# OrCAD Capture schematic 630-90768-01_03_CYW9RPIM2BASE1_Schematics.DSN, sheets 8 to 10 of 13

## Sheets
8 05. CM4 HDMI & Fan Control: size B
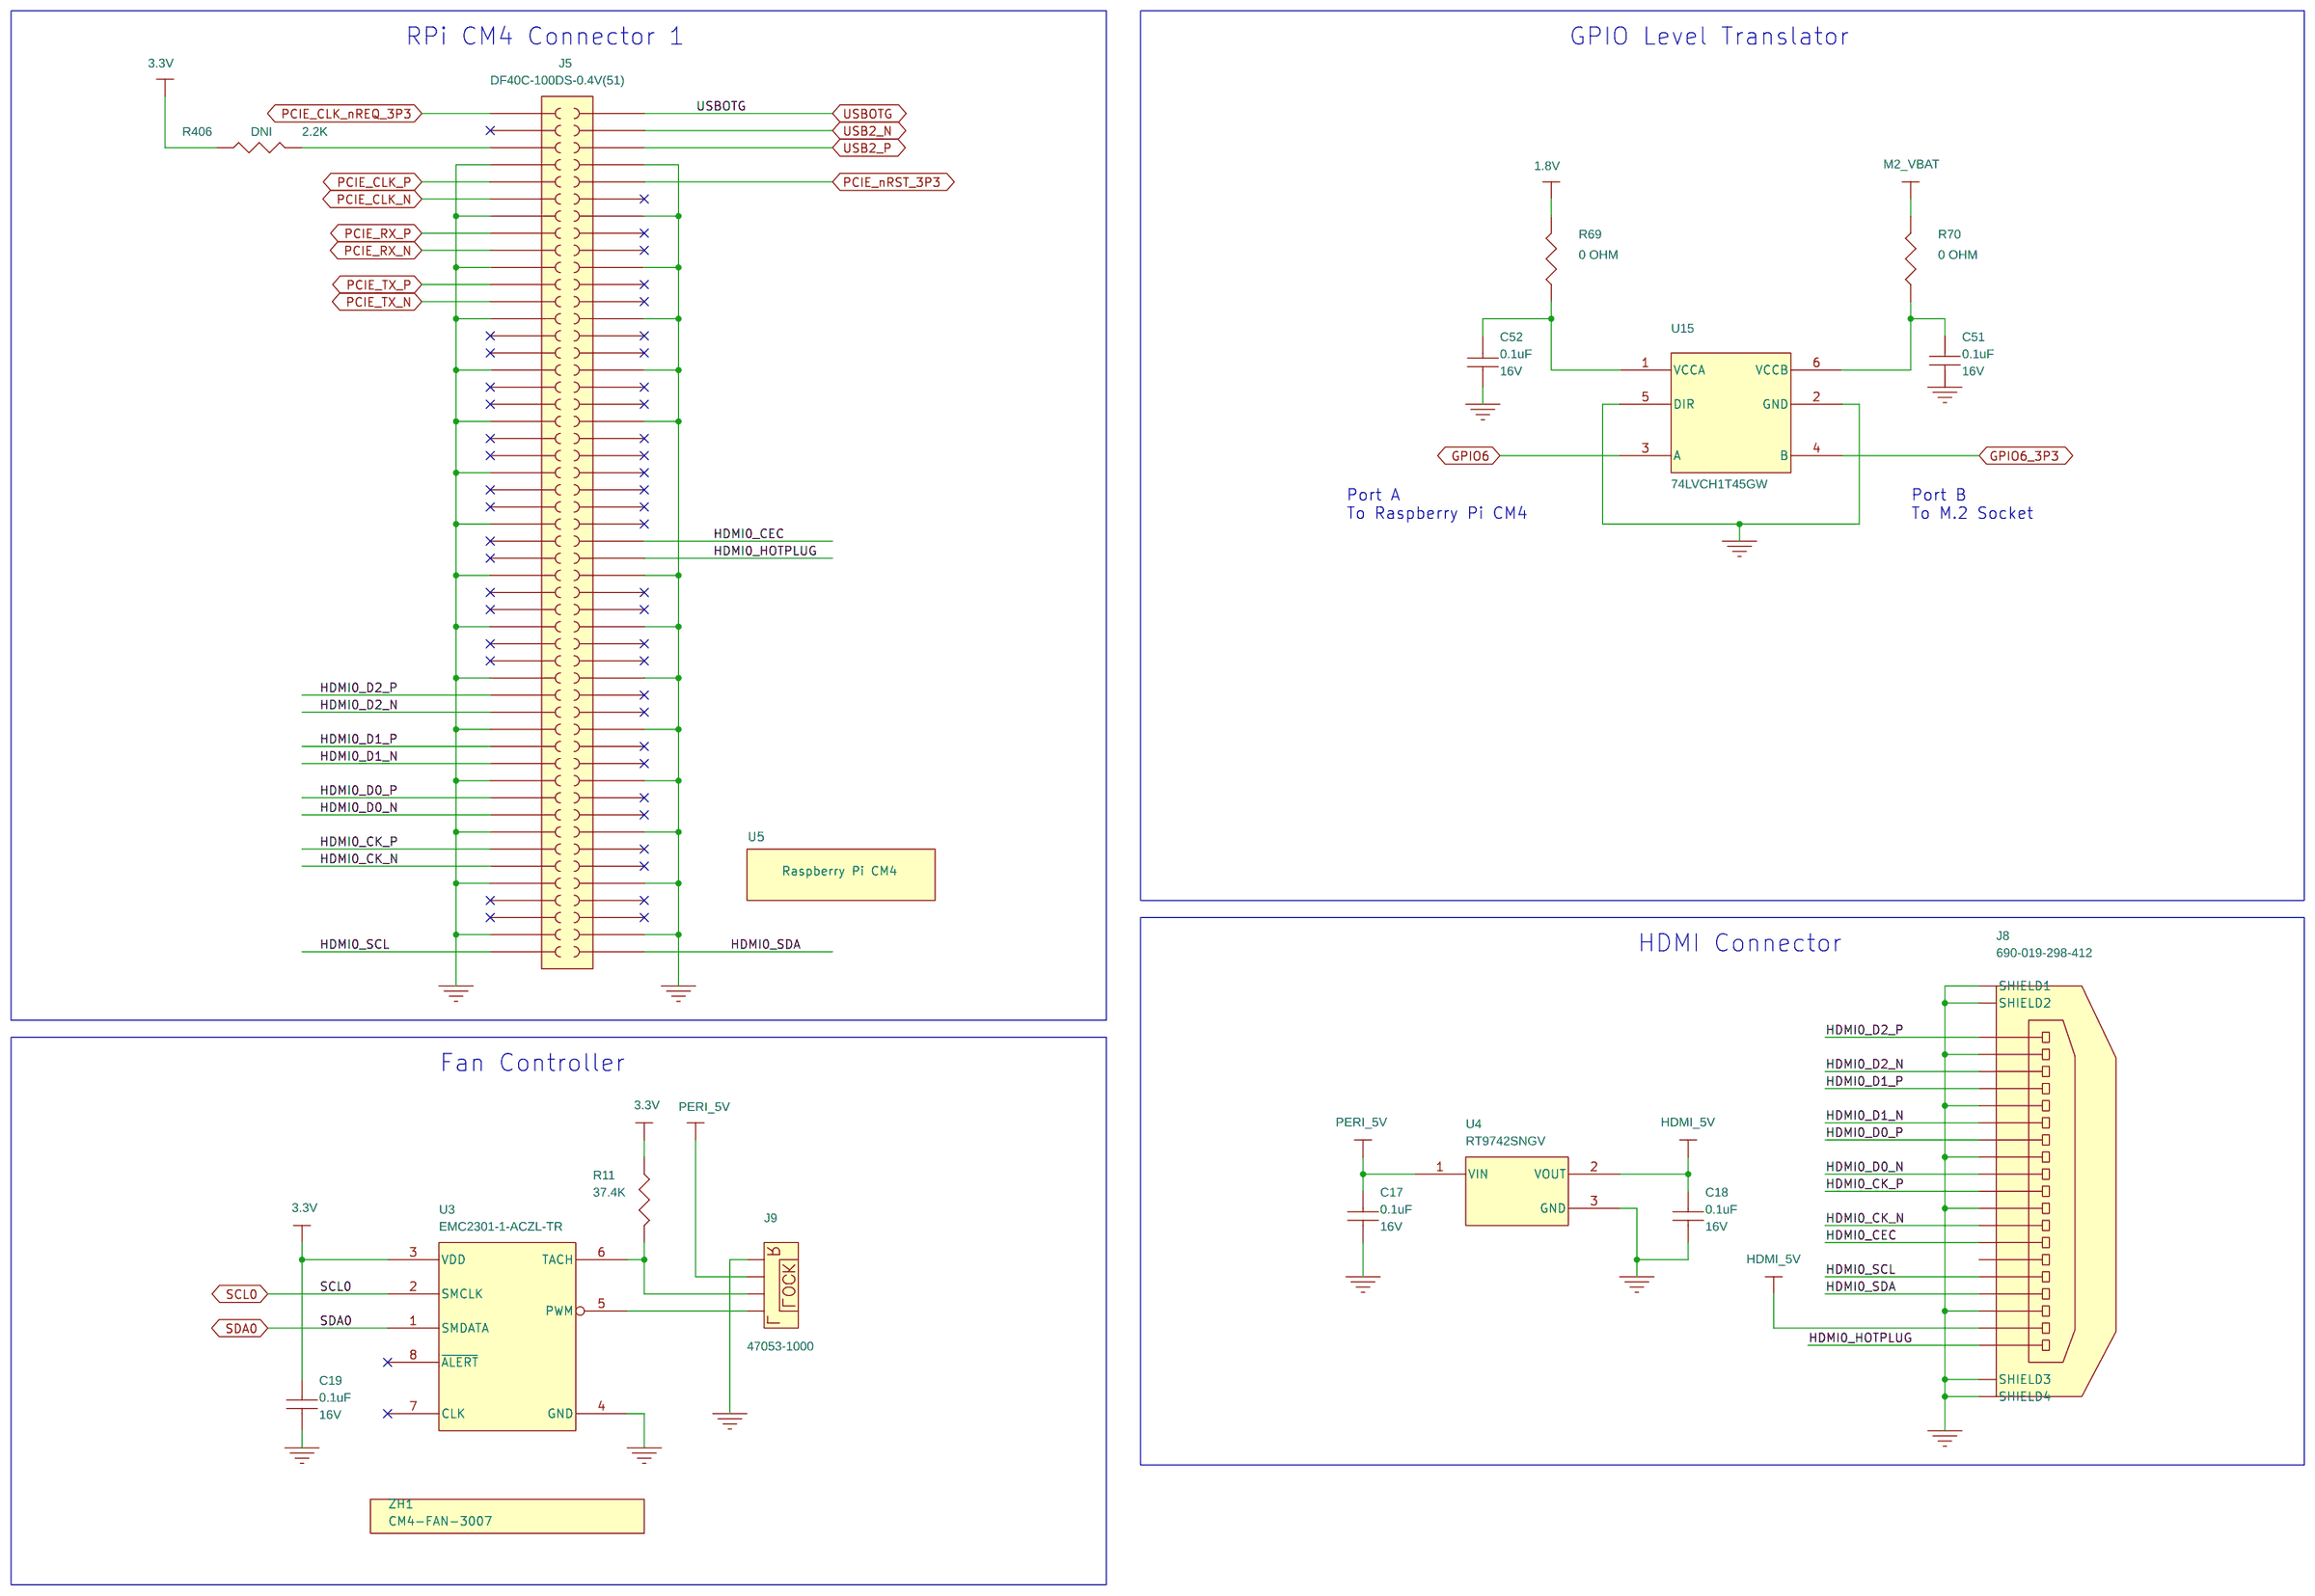
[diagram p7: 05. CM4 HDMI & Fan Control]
9 06. CM4 GPIO & Ethernet: size B
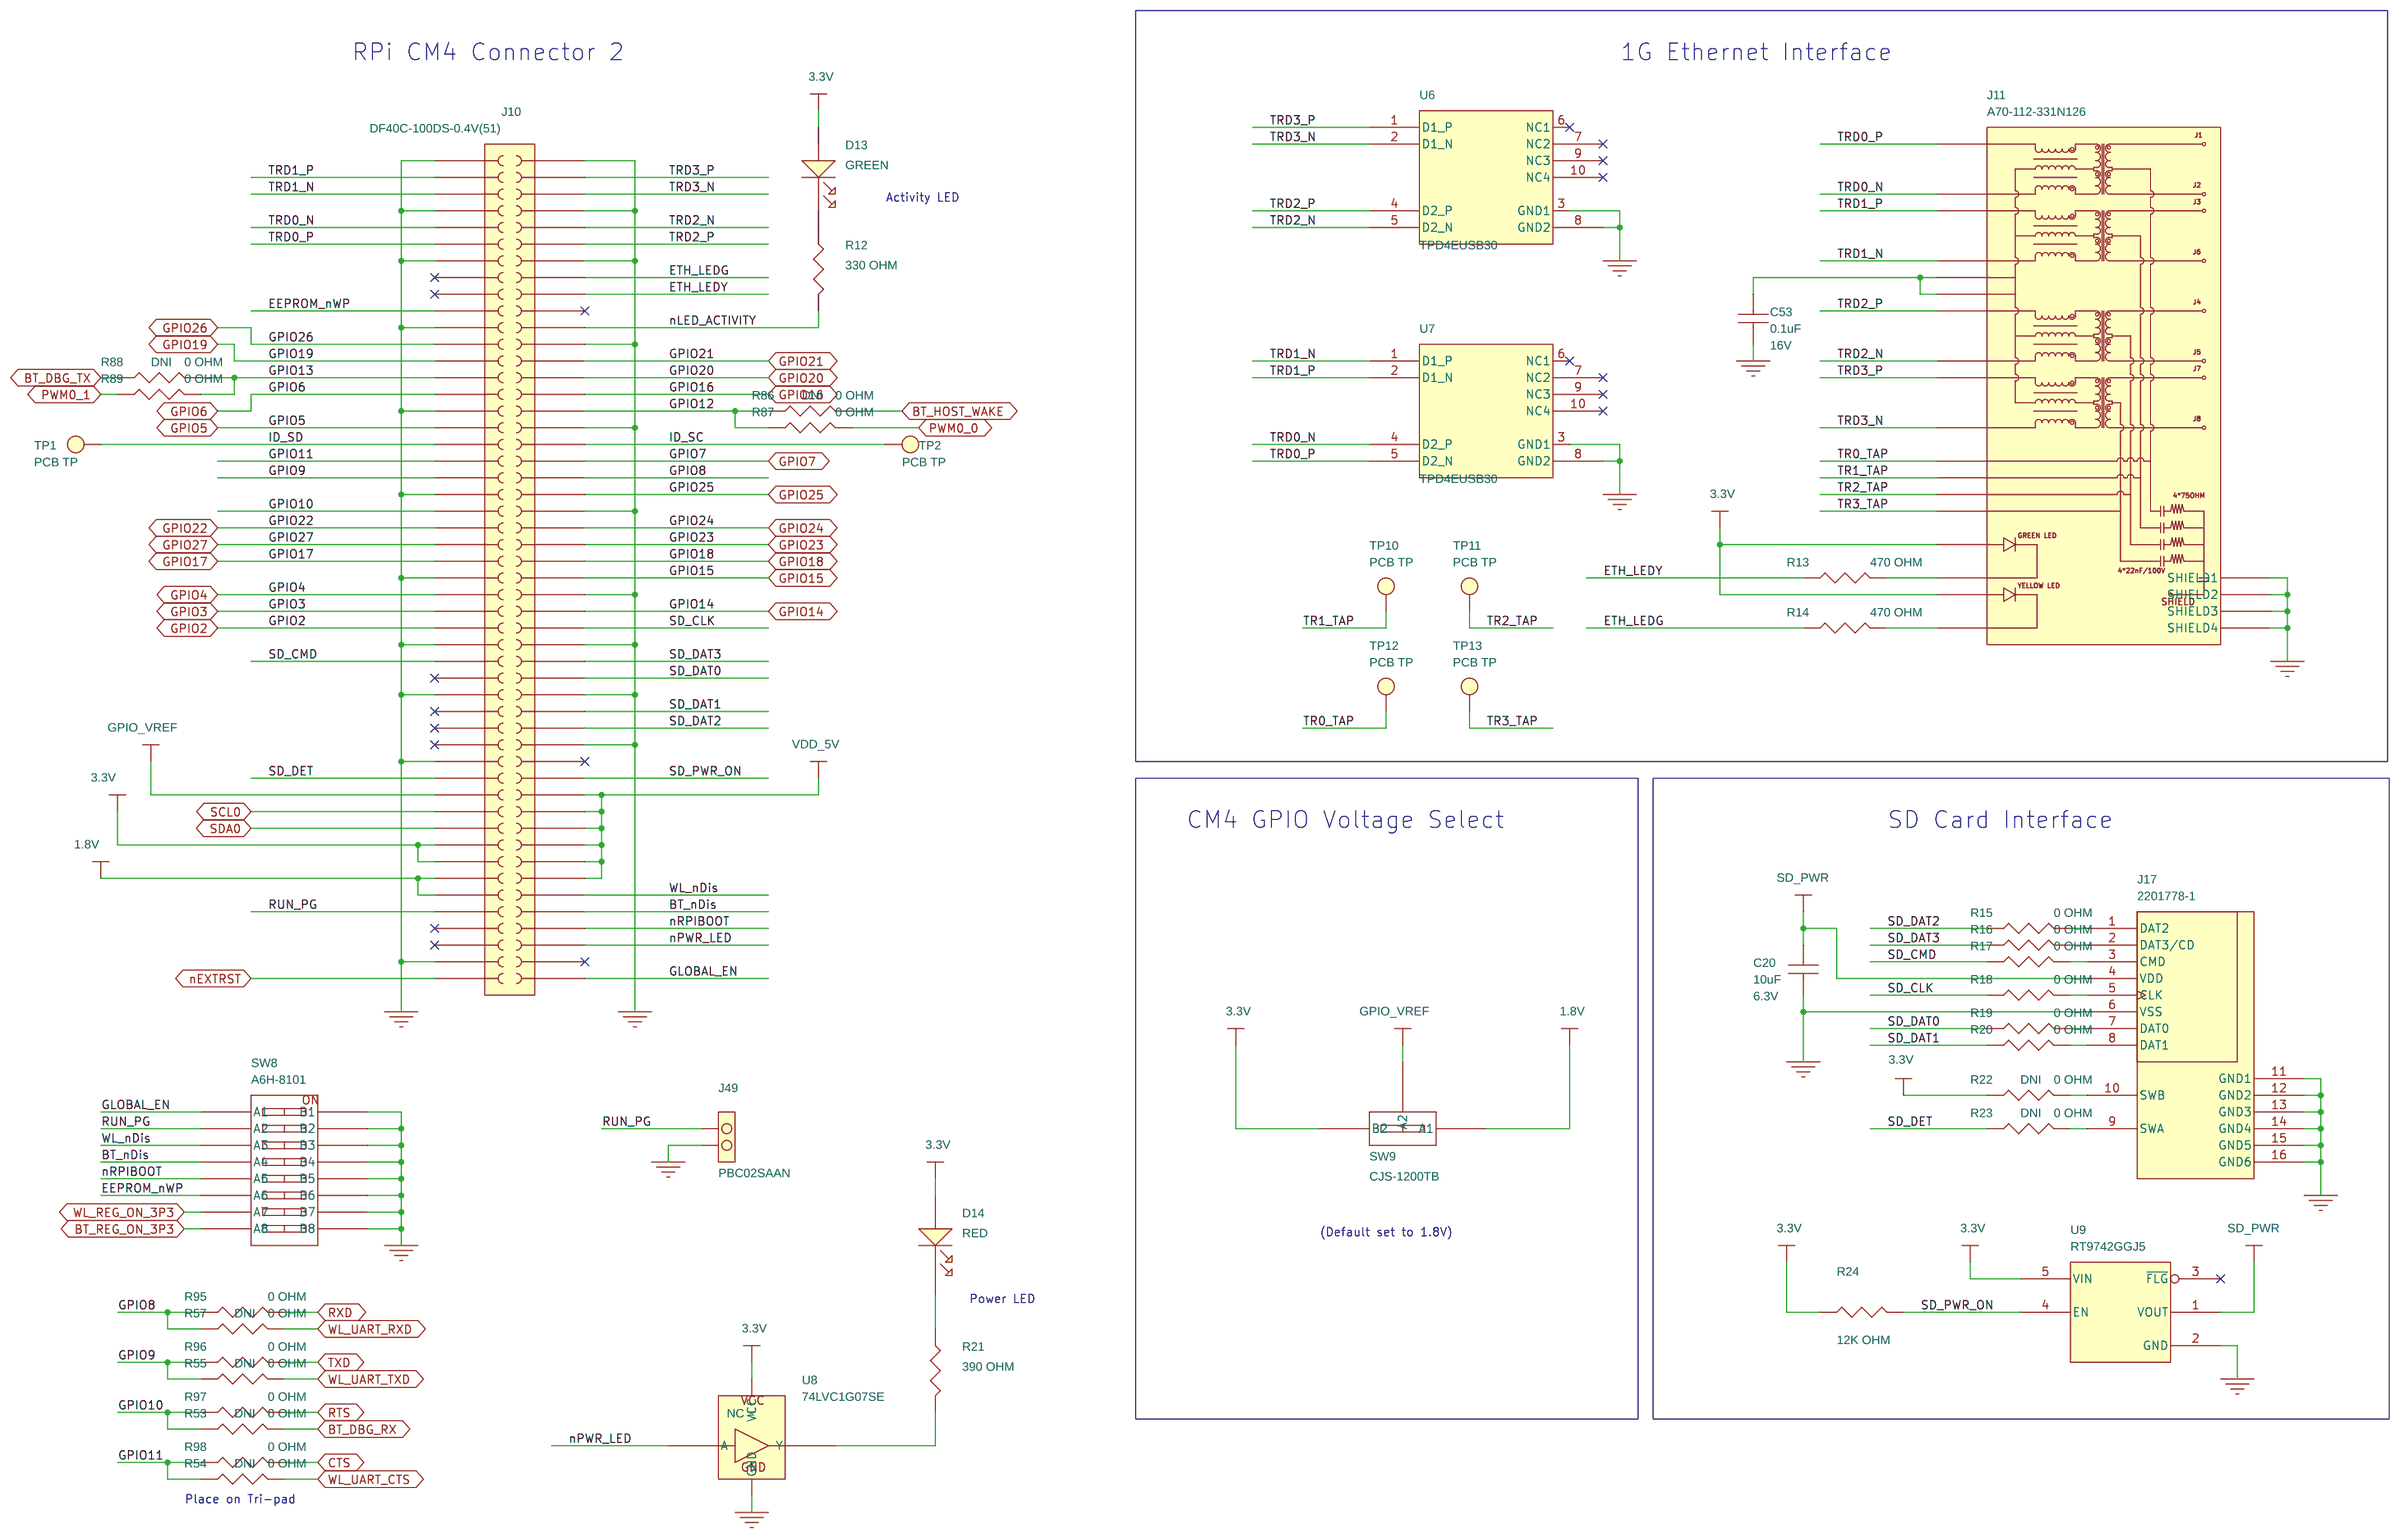
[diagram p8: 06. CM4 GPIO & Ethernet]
10 07. M.2 Interface: size B
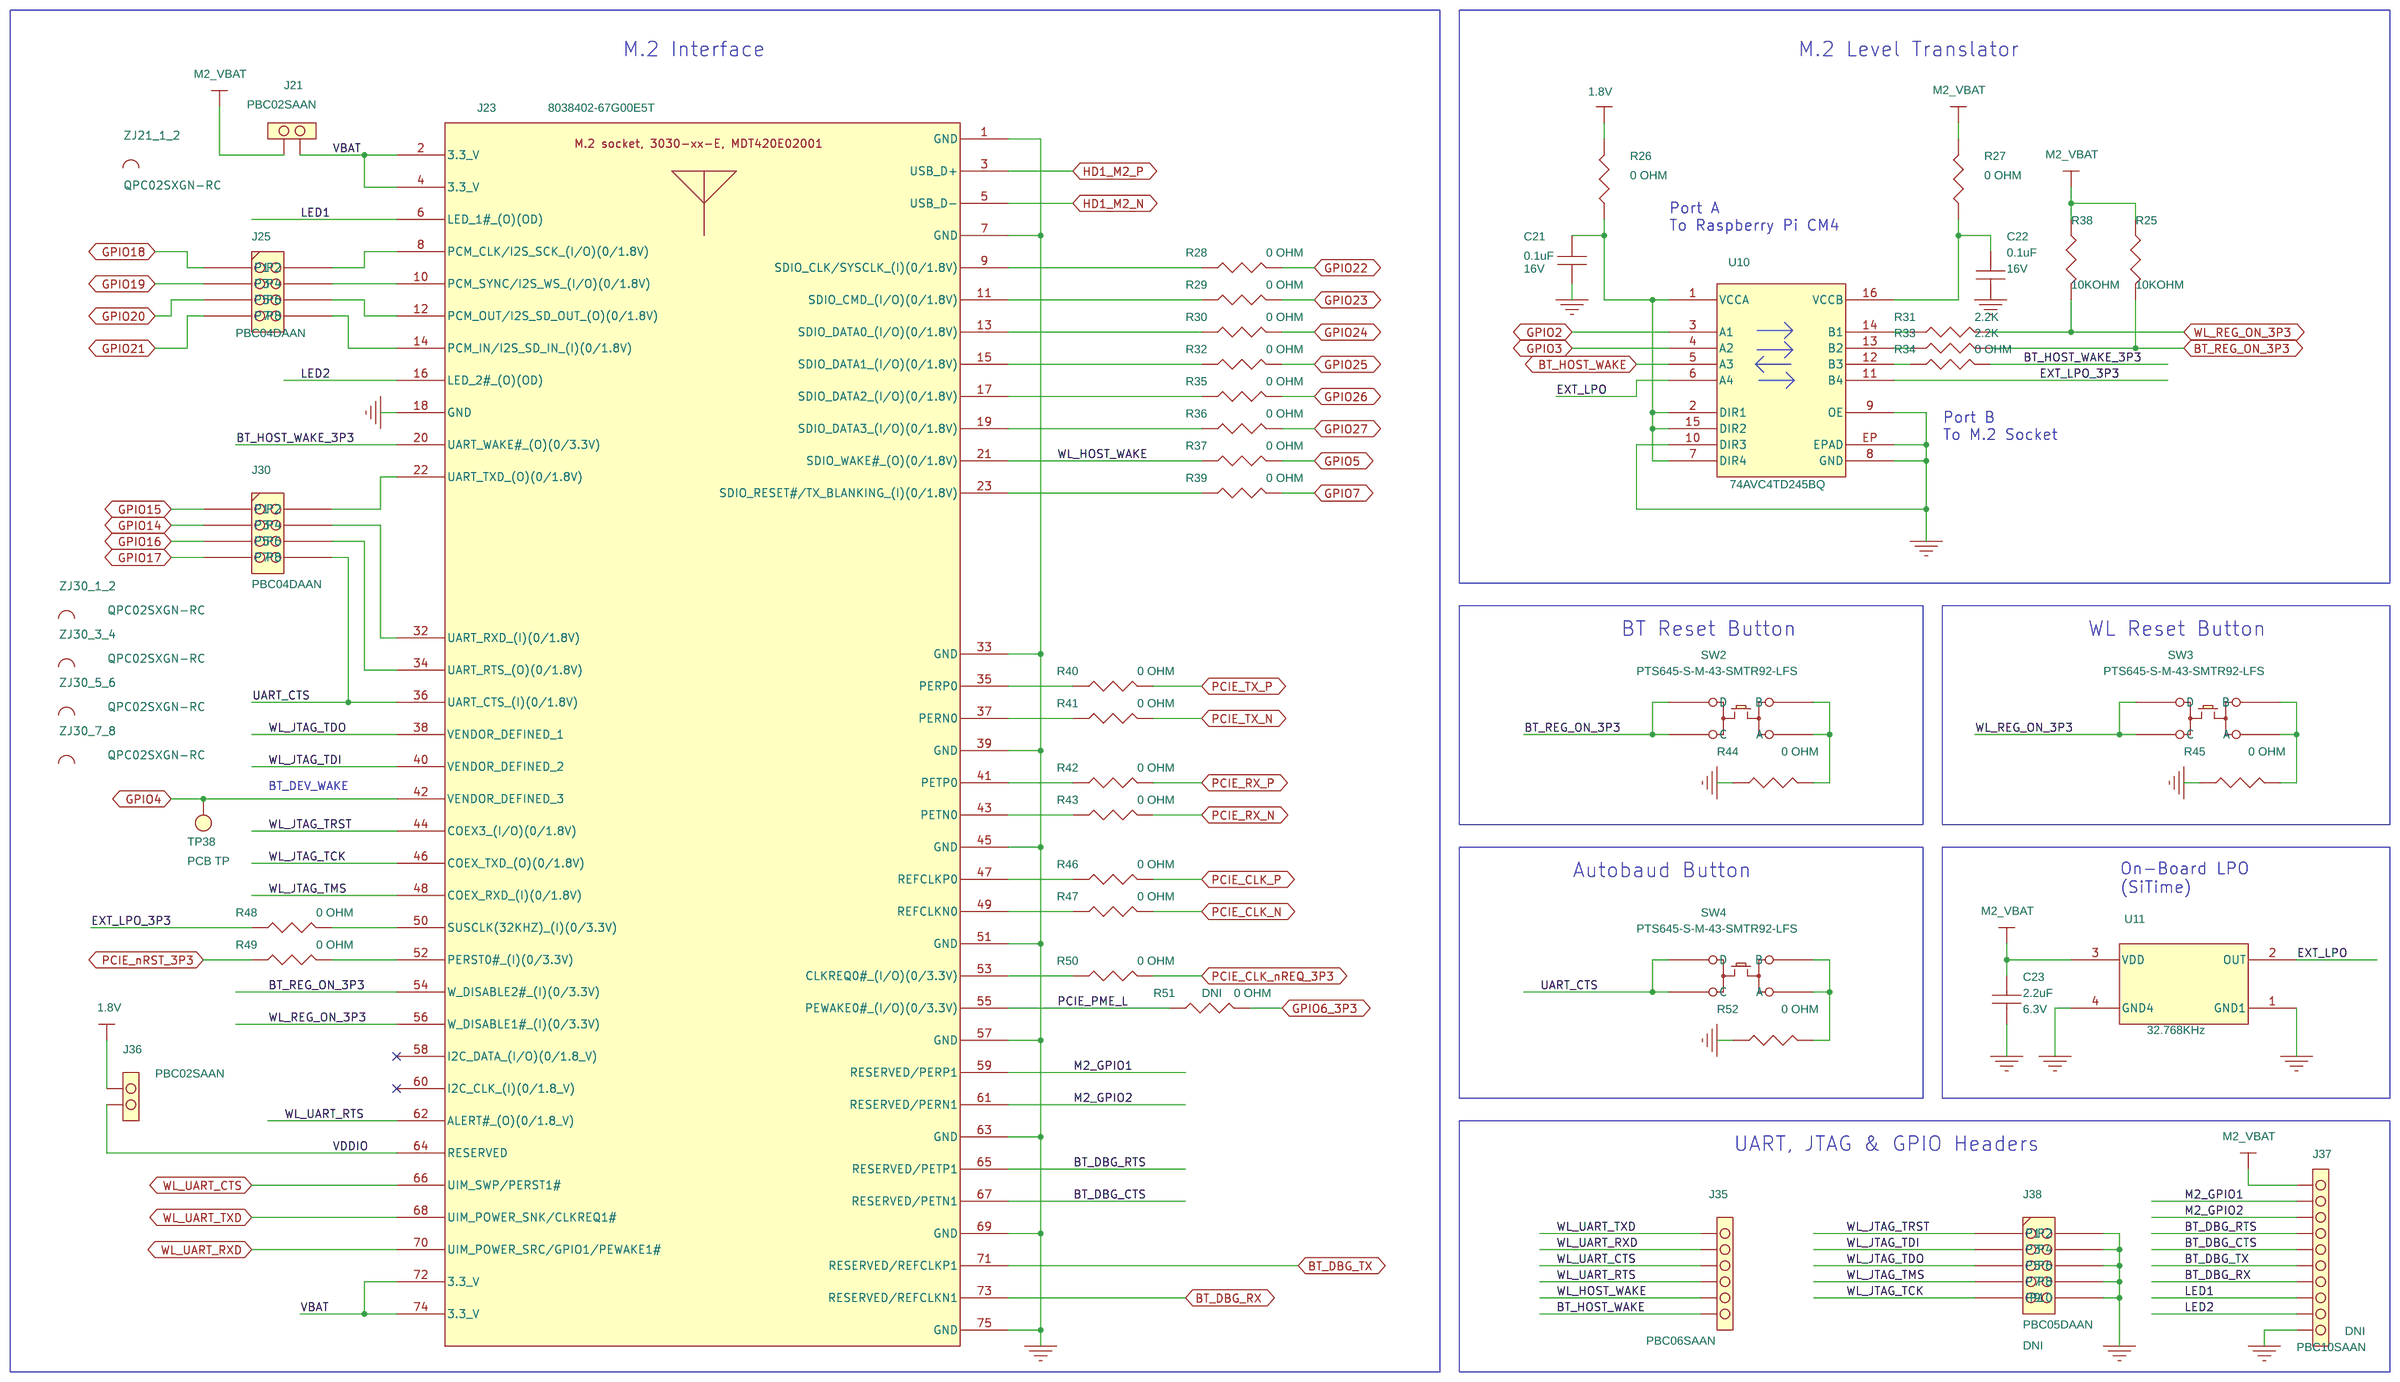
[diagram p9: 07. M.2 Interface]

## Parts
sheet 05. CM4 HDMI & Fan Control
C17  0.1uF  [CAPC1005_IS0402Q]
C18  0.1uF  [CAPC1005_IS0402Q]
C19  0.1uF  [CAPC1005_IS0402Q]
C51  0.1uF  [CAPC1005_IS0402Q]
C52  0.1uF  [CAPC1005_IS0402Q]
J5  DF40C-100DS-0.4V(51)  [con2x50_0p4_DF40C-100DS]
J8  690-019-298-412  [CON1X19_0P5_690-019-298-412]
J9  47053-1000  [molex_47053-1000]
R11  37.4K  [RESC1005_IS0402Q]
R69  0 OHM  [RESC1005_IS0402Q]
R70  0 OHM  [RESC1005_IS0402Q]
R406  2.2K  [RESC1005_IS0402Q]
U3  EMC2301-1-ACZL-TR  [msop65p490x110-8m]
U4  RT9742SNGV  [SOT23_1_2_3]
U5  Raspberry Pi CM4  [MOD-raspberry_PI_CM4]
U15  74LVCH1T45GW  [SC70-6_SC88-6_1_2_3_4_5_6]
ZH1  CM4-FAN-3007  [NA]
sheet 06. CM4 GPIO & Ethernet
C20  10uF  [CAPC1005_IS0402Q]
C53  0.1uF  [CAPC1005_IS0402Q]
D13  GREEN  [LEDC1608Q]
D14  RED  [LEDC1608Q]
J10  DF40C-100DS-0.4V(51)  [con2x50_0p4_DF40C-100DS]
J11  A70-112-331N126  [RJ45-A70-112-331N126]
J17  2201778-1  [CONmSD_2201778-1]
J49  PBC02SAAN  [CTST254PSS2]
R12  330 OHM  [RESC1005_IS0402Q]
R13  470 OHM  [RESC1005_IS0402Q]
R14  470 OHM  [RESC1005_IS0402Q]
R15  0 OHM  [RESC1005_IS0402Q]
R16  0 OHM  [RESC1005_IS0402Q]
R17  0 OHM  [RESC1005_IS0402Q]
R18  0 OHM  [RESC1005_IS0402Q]
R19  0 OHM  [RESC1005_IS0402Q]
R20  0 OHM  [RESC1005_IS0402Q]
R21  390 OHM  [RESC1005_IS0402Q]
R22  0 OHM  [RESC1005_IS0402Q]
R23  0 OHM  [RESC1005_IS0402Q]
R24  12K OHM  [RESC1005_IS0402Q]
R53  0 OHM  [RESC1005_IS0402Q]
R54  0 OHM  [RESC1005_IS0402Q]
R55  0 OHM  [RESC1005_IS0402Q]
R57  0 OHM  [RESC1005_IS0402Q]
R86  0 OHM  [RESC1005_IS0402Q]
R87  0 OHM  [RESC1005_IS0402Q]
R88  0 OHM  [RESC1005_IS0402Q]
R89  0 OHM  [RESC1005_IS0402Q]
R95  0 OHM  [RESC1005_IS0402Q]
R96  0 OHM  [RESC1005_IS0402Q]
R97  0 OHM  [RESC1005_IS0402Q]
R98  0 OHM  [RESC1005_IS0402Q]
SW8  A6H-8101  [SWDPS16_OMRON_A6H-8101]
SW9  CJS-1200TB  [SWDPS2_CJS]
TP1  PCB TP  [tp102c]
TP2  PCB TP  [tp102c]
TP10  PCB TP  [tp102c]
TP11  PCB TP  [tp102c]
TP12  PCB TP  [tp102c]
TP13  PCB TP  [tp102c]
U6  TPD4EUSB30  [uson10_p100x250_050mm]
U7  TPD4EUSB30  [uson10_p100x250_050mm]
U8  74LVC1G07SE  [sot65p210x215-6m]
U9  RT9742GGJ5  [tsot23-5_1_2_3_4_5]
sheet 07. M.2 Interface
C21  0.1uF  [CAPC1005_IS0402Q]
C22  0.1uF  [CAPC1005_IS0402Q]
C23  2.2uF  [CAPC1005_IS0402Q]
J21  PBC02SAAN  [CTST254PSS2]
J23  8038402-67G00E5T  [M_2_2230-XX-E_MDT420E02001]
J25  PBC04DAAN  [CTST254PDS8]
J30  PBC04DAAN  [CTST254PDS8]
J35  PBC06SAAN  [CTST254PSS6]
J36  PBC02SAAN  [CTST254PSS2]
J37  PBC10SAAN  [CTST254PSS10]
J38  PBC05DAAN  [CTST254PDS10]
R25  10KOHM  [RESC1005_IS0402Q]
R26  0 OHM  [RESC1005_IS0402Q]
R27  0 OHM  [RESC1005_IS0402Q]
R28  0 OHM  [RESC1005_IS0402Q]
R29  0 OHM  [RESC1005_IS0402Q]
R30  0 OHM  [RESC1005_IS0402Q]
R31  2.2K  [RESC1005_IS0402Q]
R32  0 OHM  [RESC1005_IS0402Q]
R33  2.2K  [RESC1005_IS0402Q]
R34  0 OHM  [RESC1005_IS0402Q]
R35  0 OHM  [RESC1005_IS0402Q]
R36  0 OHM  [RESC1005_IS0402Q]
R37  0 OHM  [RESC1005_IS0402Q]
R38  10KOHM  [RESC1005_IS0402Q]
R39  0 OHM  [RESC1005_IS0402Q]
R40  0 OHM  [RESC1005_IS0402Q]
R41  0 OHM  [RESC1005_IS0402Q]
R42  0 OHM  [RESC1005_IS0402Q]
R43  0 OHM  [RESC1005_IS0402Q]
R44  0 OHM  [RESC1005_IS0402Q]
R45  0 OHM  [RESC1005_IS0402Q]
R46  0 OHM  [RESC1005_IS0402Q]
R47  0 OHM  [RESC1005_IS0402Q]
R48  0 OHM  [RESC1005_IS0402Q]
R49  0 OHM  [RESC1005_IS0402Q]
R50  0 OHM  [RESC1005_IS0402Q]
R51  0 OHM  [RESC1005_IS0402Q]
R52  0 OHM  [RESC1005_IS0402Q]
SW2  PTS645-S-M-43-SMTR92-LFS  [swpbs4_pts645_smt]
SW3  PTS645-S-M-43-SMTR92-LFS  [swpbs4_pts645_smt]
SW4  PTS645-S-M-43-SMTR92-LFS  [swpbs4_pts645_smt]
TP38  PCB TP  [tp102c]
U10  74AVC4TD245BQ  [qfn50p350x250_16_hs200x100]
U11  32.768KHz  [xtals4_1p0x0p41_1m55x0m85]
ZJ21_1_2  QPC02SXGN-RC  [NA]
ZJ30_1_2  QPC02SXGN-RC  [NA]
ZJ30_3_4  QPC02SXGN-RC  [NA]
ZJ30_5_6  QPC02SXGN-RC  [NA]
ZJ30_7_8  QPC02SXGN-RC  [NA]

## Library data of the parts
C17-C19 C21 C22 C51-C53 = CAP: CAP, CER, 0402, 0.1uF, 10%, 16V, X7R; Assembly Instructions: <Assembly Instructions>; BRCM PN: 520157-00; CYPN: 510-90749-01; Enviromental: RoHS; FPLIST: CAPC1005_IS0402Q,CAPC1005_IS0402N,capc1005_is0402q_HP; PART TYPE: Ceramic Capacitor; Size: 0402; Status: APPROVED; TC: X7R; Tolerance: 10%; VOLTAGE: 16V; vendor_1: DARFON; vendor_2: DARFON; vendor_3: Walsin; vendor_4: Samsung; vendor_5: Murata Electronics North America; vendor_part_number_1: C1005X7R104KETS; vendor_part_number_2: C1005X7R104KETA; vendor_part_number_3: 0402B104K160CT; vendor_part_number_4: CL05B104KO5NNNC; vendor_part_number_5: GRM155R71C104KA88D -NRND-; Datasheet: \\shasdv005.infineon.com\CMU\CMU_ORCAD_CIS_LIB\CYPRESS_CIS_DATABASE\datasheet\Murata_GRM155R71C104KA88D.pdf
J5 J10 = SKT_100_ODD_EVEN_J: CONN, BOARD TO BOARD/BOARD TO FPC, RECEPTACLE, 2X50, 0.4MM PITCH, 1.5MM STACKING HEIGHT, V/T, SMT; Assembly Instructions: <Assembly Instructions>; CYPN: 720-90645-01; Enviromental: RoHS; PART TYPE: HEADER_FEMALE; Status: APPROVED; vendor_1: HIROSE; Datasheet: \\shasdv005.infineon.com\CMU\CMU_ORCAD_CIS_LIB\CYPRESS_CIS_DATABASE\datasheet\DF40C-100DS-0.4V(51).pdf
J8 = CONN_HDMI_TYPE-A_19P: CON, HDMI, TYPE A, F, R/A, 19 POS, 0.5mm PITCH, 15.0x12.14x6.08mm, SMT; Assembly Instructions: <Assembly Instructions>; CYPN: 720-90650-01; Enviromental: RoHS; PART TYPE: HDMI; Status: APPROVED; vendor_1: EDAC; Datasheet: \\shasdv005.infineon.com\CMU\CMU_ORCAD_CIS_LIB\CYPRESS_CIS_DATABASE\datasheet\690-019-298-412.pdf
J9 = HDR1X4-LOCK-1R-J: CON, HDR, T/H, M, STR, 1x4P, 2.54mm PITCH, 3.5mmTL, 7.5mmPH, W/FRICTION; Assembly Instructions: <Assembly Instructions>; CYPN: 710-90172-01; Enviromental: RoHS; PART TYPE: HEADER_MALE; Status: APPROVED; vendor_1: Molex; Datasheet: \\shasdv005.infineon.com\CMU\CMU_ORCAD_CIS_LIB\CYPRESS_CIS_DATABASE\datasheet\470531000_sd.pdf
R11 = RES: RES, THK, 0402, 37.4K, 1%, 63mW, 50V; Assembly Instructions: <Assembly Instructions>; BRCM PN: 551066-00; CYPN: 500-91030-01; Enviromental: RoHS; FPLIST: RESC1005_IS0402Q,RESC1005_IS0402N; PART TYPE: THICK FILM; Size: 0402; Status: APPROVED; Tolerance: 1%; vendor_1: CYNTEC; vendor_2: VIKING TECH; vendor_3: Walsin; vendor_4: Yageo America; vendor_part_number_1: PFR05S-3742-FNH; vendor_part_number_2: CR-02FL6--37K4AC; vendor_part_number_3: WR04X3742FTL; vendor_part_number_4: RC0402FR-0737K4L; Datasheet: \\shasdv005.infineon.com\CMU\CMU_ORCAD_CIS_LIB\CYPRESS_CIS_DATABASE\datasheet\RC0402FR-0737K4L.pdf
R26 R27 R69 R70 = RES: RES, THK, 0402, 0, 1%, HI POWER, 125mW; BRCM PN: 553942-00; CYPN: 500-90992-01; Enviromental: RoHS; FPLIST: RESC1005_IS0402Q,RESC1005_IS0402N; PART TYPE: THICK FILM; Size: 0402; Status: APPROVED; Tolerance: 1%; vendor_1: VISHAY; vendor_2: Walsin; vendor_part_number_1: CRCW04020000Z0EDHP; vendor_part_number_2: WF04P000PTL; Datasheet: \\shasdv005.infineon.com\CMU\CMU_ORCAD_CIS_LIB\CYPRESS_CIS_DATABASE\datasheet\CRCW04020000Z0EDHP.pdf
R406 = RES: RES, THK, 0402, 2.2K OHM, 5%, 63mW; Assembly Instructions: <Assembly Instructions>; BRCM PN: 559975-00; CYPN: 500-90839-01; DNI: DNI; Enviromental: RoHS; FPLIST: RESC1005_IS0402Q,RESC1005_IS0402N; PART TYPE: THICK FILM; Size: 0402; Status: APPROVED; Tolerance: 5%; vendor_1: CYNTEC; vendor_2: KOA Speer Electronics; vendor_3: Panasonic-ECG; vendor_4: RALEC; vendor_5: VIKING TECH; vendor_6: Walsin; vendor_part_number_1: PFR05S-222-JNH; vendor_part_number_2: RK73B1ETTP222J; vendor_part_number_3: ERJ-2GEJ222X; vendor_part_number_4: RTT02222JTH; vendor_part_number_5: CR-02JL6---2K2AC; vendor_part_number_6: WR04X222 JTL
U3 = EMC2301_MSOP8: IC, Single RPM-Based PWM Fan Controller, MSOP-8P; Assembly Instructions: <Assembly Instructions>; CYPN: 450-90680-01; Enviromental: RoHS; PART TYPE: CONTROLLER; Status: APPROVED; vendor_1: Microchip Technology; Datasheet: \\shasdv005.infineon.com\CMU\CMU_ORCAD_CIS_LIB\CYPRESS_CIS_DATABASE\datasheet\EMC2301-1-ACZL-TR.pdf
U4 = RT9742SNGV_SOT23_3: IC, POWER SWH, HIGH-SIDE, W/FLAG, 2.7V/6V, 0.5A, SOT23-3; Assembly Instructions: <Assembly Instructions>; CYPN: 450-90672-01; Enviromental: RoHS; PART TYPE: SWITCH; Status: APPROVED; vendor_1: Richtek USA Inc; Datasheet: \\shasdv005.infineon.com\CMU\CMU_ORCAD_CIS_LIB\CYPRESS_CIS_DATABASE\datasheet\RT9742SNGV.pdf
U5 = Raspberry_Pi_CM4: MOD, Raspberry Pi Compute Module 4 (CM4); Assembly Instructions: <Assembly Instructions>; CYPN: 450-90674-01; Enviromental: RoHS; PART TYPE: Compute; Status: APPROVED; vendor_1: Raspberry Pi; vendor_part_number_1: Compute Module 4; Datasheet: \\shasdv005.infineon.com\CMU\CMU_ORCAD_CIS_LIB\CYPRESS_CIS_DATABASE\datasheet\cm4-datasheet.pdf
U15 = 74XX1T45-SO6: IC, LGC, SOT363, XLATOR, 1.2/5.5V, SINGLE, BI-DIREC, DUAL SUPPLY; Assembly Instructions: <Assembly Instructions>; BRCM PN: 549366-00; CYPN: 430-90009-01; Enviromental: Green HF; PART TYPE: TRANSLATOR; Status: APPROVED; vendor_1: Nexperia; vendor_2: Nexperia; vendor_part_number_1: 74LVCH1T45GW,125
ZH1 = ZH: HARDWARE, Dedicated 3007 Cooling Fan for Raspberry Pi Compute Module 4 CM4, Low Noise; Assembly Instructions: <Assembly Instructions>; CYPN: 700-90170-01; Enviromental: RoHS; FPLIST: NA,HARDWARE; PART TYPE: Fan; Status: APPROVED; vendor_1: Waveshare; Datasheet: \\shasdv005.infineon.com\CMU\CMU_ORCAD_CIS_LIB\CYPRESS_CIS_DATABASE\datasheet\CM4-FAN-3007.pdf
C20 = CAP: CAP, CER, 0402, 10uF, 20%, 6.3V, X5R; Assembly Instructions: <Assembly Instructions>; BRCM PN: 543921-00; CYPN: 510-90758-01; Enviromental: RoHS; FPLIST: CAPC1005_IS0402Q,CAPC1005_IS0402N; PART TYPE: Ceramic Capacitor; Size: 0402; Status: APPROVED; TC: X5R; Tolerance: 20%; VOLTAGE: 6.3V; vendor_1: DARFON; vendor_2: Murata; vendor_3: Murata; vendor_4: Walsin; vendor_part_number_1: C1005X5R106MCTS; vendor_part_number_2: GRM155R60J106ME44D-EOL; vendor_part_number_3: GRM155R60J106ME15D; vendor_part_number_4: 0402X106M6R3CT; Datasheet: \\shasdv005.infineon.com\CMU\CMU_ORCAD_CIS_LIB\CYPRESS_CIS_DATABASE\datasheet\GRM155R60J106ME44D.pdf
D13 = DIO-LED: DIO, LED, 0603, 2.2V, 20mA, GREEN, CLEAR, STR, 0.75mm; Assembly Instructions: <Assembly Instructions>; BRCM PN: 546241-00; CYPN: 534-90153-01; Current: 20mA; Enviromental: RoHS; PART TYPE: LED; Status: APPROVED; VOLTAGE: 2.2V; vendor_1: Kingbright; vendor_part_number_1: APT1608SGC; Datasheet: \\shasdv005.infineon.com\CMU\CMU_ORCAD_CIS_LIB\CYPRESS_CIS_DATABASE\datasheet\APT1608SGC(Ver.20B).pdf
D14 = DIO-LED: LED, 0603, 2.2V, 30mA, RED, STR, 1.8mcd, 130DEG; Assembly Instructions: <Assembly Instructions>; BRCM PN: 534363-00; CYPN: 530-90157-01; Current: 30mA; Enviromental: RoHS; PART TYPE: LED; Status: APPROVED; VOLTAGE: 2.2V; vendor_1: Lite On, Inc; vendor_2: Broadcom; vendor_part_number_1: LTST-C193KRKT-2A; vendor_part_number_2: QSMC-C133; Datasheet: \\shasdv005.infineon.com\CMU\CMU_ORCAD_CIS_LIB\CYPRESS_CIS_DATABASE\datasheet\QSMC-C133.rar
J11 = CONN_RJ45_10P_2LED: CON, RJ45, 10 POS, 1PORT, WITH G/Y LED, T/H, F, R/A, 8C SHIELDED/10/100/1000 Mbps FILTER WITH PoE; Assembly Instructions: <Assembly Instructions>; CYPN: 720-90648-01; Enviromental: RoHS; PART TYPE: RJ45; Status: APPROVED; vendor_1: EDAC; Datasheet: \\shasdv005.infineon.com\CMU\CMU_ORCAD_CIS_LIB\CYPRESS_CIS_DATABASE\datasheet\A70-112-331N126.pdf
J17 = CONN_uSD_2201778-1: CON, MICRO-SD, F, R/A, 8 POS, PUSH/PUSH, WITHOUT MYLAR, SMT; Assembly Instructions: <Assembly Instructions>; CYPN: 720-90651-01; Enviromental: RoHS; PART TYPE: SD SOCKET; Status: APPROVED; vendor_1: TE Connectivity; Datasheet: \\shasdv005.infineon.com\CMU\CMU_ORCAD_CIS_LIB\CYPRESS_CIS_DATABASE\datasheet\ENG_CD_2201778_C.pdf
J21 J36 J49 = HDR1X2-J: CON, HDR, T/H, M, STR, 1x2P, 2.54mm, 3.05mmTL, 5.84mmPH, BREAKAWAY; BRCM PN: 520019-00; CYPN: 720-90456-01; Enviromental: RoHS; PART TYPE: HEADER_MALE; Status: APPROVED; vendor_1: Sullins Connector Solutions; vendor_2: TE Connectivity; vendor_3: Molex; vendor_4: Ting Chou Metal Wire (??); vendor_part_number_2: 4-103327-4; vendor_part_number_3: 22-28-4020; vendor_part_number_4: 25401S1G002A101; Datasheet: \\shasdv005.infineon.com\CMU\CMU_ORCAD_CIS_LIB\CYPRESS_CIS_DATABASE\datasheet\Molex_DS_22-28-4020.pdf
R12 = RES: RES, THK, 0402, 330 OHM, 5%, 63mW; CYPN: 500-90868-01; Enviromental: RoHS; FPLIST: RESC1005_IS0402Q,RESC1005_IS0402N; PART TYPE: THICK FILM; Size: 0402; Status: APPROVED; Tolerance: 5%; vendor_1: CYNTEC; vendor_2: CYNTEC; vendor_3: Panasonic-ECG; vendor_4: RALEC; vendor_5: VIKING TECH; vendor_6: Walsin; vendor_7: Yageo America; vendor_part_number_1: RR0510S-331-JNH; vendor_part_number_2: PFR05S-331-JNH; vendor_part_number_3: ERJ-2GEJ331X; vendor_part_number_4: RTT02331JTH; vendor_part_number_5: CR-02JL6--330RAC; vendor_part_number_6: WR04X331 JTL; vendor_part_number_7: RC0402JR-07330RL; Datasheet: \\shasdv005.infineon.com\CMU\CMU_ORCAD_CIS_LIB\CYPRESS_CIS_DATABASE\datasheet\Panasonic_ERJ-2GEJ331X.pdf
R13 R14 = RES: RES, THK, 0402, 470 OHM, 1%, 63mW; Assembly Instructions: <Assembly Instructions>; CYPN: 500-91112-01; Enviromental: RoHS; FPLIST: RESC1005_IS0402Q,RESC1005_IS0402N; PART TYPE: THICK FILM; Size: 0402; Status: APPROVED; Tolerance: 1%; vendor_1: CYNTEC; vendor_2: VIKING TECH; vendor_3: Walsin; vendor_part_number_1: RR0510S-471-FNH; vendor_part_number_2: CR-02FL6--470RAC; vendor_part_number_3: WR04X4700FTL; Datasheet: \\shasdv005.infineon.com\CMU\CMU_ORCAD_CIS_LIB\CYPRESS_CIS_DATABASE\datasheet\WR04X4700FTL.pdf
R15-R20 R28-R30 R32 R34-R37 R39-R50 R52 R87 R89 R95-R98 = RES: RES, THK, 0402, 0 OHM, 63mW; Assembly Instructions: <Assembly Instructions>; BRCM PN: 500225-00; CYPN: 500-90842-01; Enviromental: RoHS; FPLIST: RESC1005_IS0402Q,RESC1005_IS0402N; PART TYPE: THICK FILM; Size: 0402; Status: APPROVED; Tolerance: 5%; vendor_1: Walsin; vendor_2: CYNTEC; vendor_3: KOA Speer Electronics; vendor_4: Panasonic-ECG; vendor_5: VIKING TECH; vendor_6: Yageo America; vendor_part_number_1: WR04X000 PTL; vendor_part_number_2: PFR05X-000-XNH; vendor_part_number_3: RK73Z1ETQTP; vendor_part_number_4: ERJ-2GE0R00X; vendor_part_number_5: CR-02JL6----0RAC; vendor_part_number_6: RC0402JR-070RL
R21 = RES: RES, THK, 0402, 390 OHM, 5%, 63mW; BRCM PN: 520333-00; CYPN: 500-90925-01; Enviromental: RoHS; FPLIST: RESC1005_IS0402Q,RESC1005_IS0402N; PART TYPE: THICK FILM; Size: 0402; Status: APPROVED; Tolerance: 5%; vendor_1: VIKING TECH; vendor_2: Walsin; vendor_3: Yageo America; vendor_4: Yageo America; vendor_part_number_1: CR-02JL6--390RAC; vendor_part_number_2: WR04X391 JTL; vendor_part_number_3: RC0402JK-07390RL; vendor_part_number_4: RC0402JR-07390RL; Datasheet: \\shasdv005.infineon.com\CMU\CMU_ORCAD_CIS_LIB\CYPRESS_CIS_DATABASE\datasheet\ / CR..AC REV.A.pdf
R22 R23 R51 R53-R55 R57 R86 R88 = RES: RES, THK, 0402, 0 OHM, 63mW; Assembly Instructions: <Assembly Instructions>; BRCM PN: 500225-00; CYPN: 500-90842-01; DNI: DNI; Enviromental: RoHS; FPLIST: RESC1005_IS0402Q,RESC1005_IS0402N; PART TYPE: THICK FILM; Size: 0402; Status: APPROVED; Tolerance: 5%; vendor_1: Walsin; vendor_2: CYNTEC; vendor_3: KOA Speer Electronics; vendor_4: Panasonic-ECG; vendor_5: VIKING TECH; vendor_6: Yageo America; vendor_part_number_1: WR04X000 PTL; vendor_part_number_2: PFR05X-000-XNH; vendor_part_number_3: RK73Z1ETQTP; vendor_part_number_4: ERJ-2GE0R00X; vendor_part_number_5: CR-02JL6----0RAC; vendor_part_number_6: RC0402JR-070RL
R24 = RES: RES, THK, 0402, 12K OHM, 1%, 63mW; Assembly Instructions: <Assembly Instructions>; CYPN: 500-90852-01; Enviromental: RoHS; FPLIST: RESC1005_IS0402Q,RESC1005_IS0402N; PART TYPE: THICK FILM; Size: 0402; Status: APPROVED; Tolerance: 1%; vendor_1: CYNTEC; vendor_2: RALEC; vendor_3: VIKING TECH; vendor_4: Walsin; vendor_5: Yageo America; vendor_part_number_1: PFR05S-1202-FNH; vendor_part_number_2: RTT021202FTH; vendor_part_number_3: CR-02FL6---12KAC; vendor_part_number_4: WR04X1202FTL; vendor_part_number_5: RC0402FR-0712KL; Datasheet: \\shasdv005.infineon.com\CMU\CMU_ORCAD_CIS_LIB\CYPRESS_CIS_DATABASE\datasheet\CR REV.C3-160715.pdf
SW8 = SW-DIP-8: SWH, SLD, DIP, SMT, STR, SPST, 8POS, 24V, 25mA, 11.39x6.7x1.45mm; Assembly Instructions: <Assembly Instructions>; BRCM PN: 559402-00; CYPN: 770-90103-01; Enviromental: RoHS; PART TYPE: DIP; Status: APPROVED; vendor_1: Omron; Datasheet: \\shasdv005.infineon.com\CMU\CMU_ORCAD_CIS_LIB\CYPRESS_CIS_DATABASE\datasheet\A6H-8101.pdf
SW9 = SW-DIP-1: SWH,DIP,SMT,STR,SPDT; Assembly Instructions: <Assembly Instructions>; CYPN: 770-90139-01; Enviromental: RoHS; PART TYPE: DIP; Status: APPROVED; vendor_1: Copal Electronics; Datasheet: \\shasdv005.infineon.com\CMU\CMU_ORCAD_CIS_LIB\CYPRESS_CIS_DATABASE\datasheet\CJS-1200TB.pdf
TP1 TP2 TP10-TP13 TP38 = TP: TESTPOINT, PCB PAD, RND,1MM, SMT; Assembly Instructions: DNI; CYPN: TP-SMT-100-RND; PART TYPE: TEST-POINT
U6 U7 = TPD4EUSB30_USON10: DIO, TVS, Uni-Dir, 4-Channel, ESD Protection, for Super-Speed USB 3.0 Interface, USON-10; Assembly Instructions: <Assembly Instructions>; CYPN: 530-90204-01; Enviromental: RoHS; PART TYPE: TVS; Status: APPROVED; vendor_1: Texas Instruments; vendor_part_number_1: TPD4EUSB30DQAR; Datasheet: \\shasdv005.infineon.com\CMU\CMU_ORCAD_CIS_LIB\CYPRESS_CIS_DATABASE\datasheet\tpd4eusb30.pdf
U8 = BUF-1: IC, SINGLE BUFFER/DRIVER, 1-CH, WITH OPEN DRAIN OUTPUT, 1.65/5.5V, 5 PIN, SOT353; Assembly Instructions: <Assembly Instructions>; CYPN: 450-90675-01; Enviromental: RoHS; PART TYPE: BUFFER; Status: APPROVED; vendor_1: Diodes Inc; vendor_part_number_1: 74LVC1G07SE-7; Datasheet: \\shasdv005.infineon.com\CMU\CMU_ORCAD_CIS_LIB\CYPRESS_CIS_DATABASE\datasheet\74LVC1G07.pdf
U9 = RT9742GGJ5_TSOT23-5: IC, POWER SWH, HIGH-SIDE, W/FLAG, 2.7V/6V, 1A, TSOT-23-5; Assembly Instructions: <Assembly Instructions>; CYPN: 450-90676-01; Enviromental: RoHS; PART TYPE: SWITCH; Status: APPROVED; vendor_1: Richtek USA Inc; Datasheet: \\shasdv005.infineon.com\CMU\CMU_ORCAD_CIS_LIB\CYPRESS_CIS_DATABASE\datasheet\RT9742GGJ5.pdf
C23 = CAP: CAP, CER, 0402, 2.2uF, 20%, 6.3V, X5R, CRITICAL/SOLE SOURCE: SAMSUNG CL05A225MQ5NNNC; BRCM PN: 530568-00; CYPN: 510-91131-01; Critical: CRITICAL; Enviromental: RoHS; FPLIST: CAPC1005_IS0402Q,CAPC1005_IS0402N; PART TYPE: Ceramic Capacitor; Size: 0402; Status: APPROVED; TC: X5R; Tolerance: 20%; VOLTAGE: 6.3V; vendor_1: Samsung; vendor_part_number_1: CL05A225MQ5NNNC; Datasheet: \\shasdv005.infineon.com\CMU\CMU_ORCAD_CIS_LIB\CYPRESS_CIS_DATABASE\datasheet\CL05A225MQ5NNNC.pdf
J23 = SKT_M_2_3030-xx-E_MDT420E02001: CON, NGFF, M.2, F, R/A, 67P, 21.9x7.2x4.0mm, 0.5mm PITCH, Au, KEY E, SMT; Assembly Instructions: <Assembly Instructions>; CYPN: 720-90612-01; Enviromental: RoHS; FPLIST: M_2_2230-XX-E_MDT420E02001,M_2_3030-XX-E_MDT420E02001; PART TYPE: NGFF; Status: APPROVED; vendor_1: REGO; Datasheet: \\shasdv005.infineon.com\CMU\CMU_ORCAD_CIS_LIB\CYPRESS_CIS_DATABASE\datasheet\8038402-67G00E5T.PDF
J25 J30 = HDR2X4R-J: CON, HDR, T/H, M, STR, 2x4P, 2.54mm, 3.05mmTL, 5.84mmPH, BREAKAWAY; Assembly Instructions: <Assembly Instructions>; BRCM PN: 530900-00; CYPN: 710-90087-01; Enviromental: RoHS; PART TYPE: HEADER_MALE; Status: APPROVED; vendor_1: Sullins Connector Solutions; Datasheet: \\shasdv005.infineon.com\CMU\CMU_ORCAD_CIS_LIB\CYPRESS_CIS_DATABASE\datasheet\PBC04DAAN.pdf
J35 = HDR1X6-J: CON, HDR, T/H, M, STR, 1x6P, 2.54mm, 3.05mmTL, 5.84mmPH, BREAKAWAY; Assembly Instructions: <Assembly Instructions>; BRCM PN: 528724-00; CYPN: 720-90498-01; Enviromental: RoHS; PART TYPE: HEADER_MALE; Status: APPROVED; vendor_1: Sullins Connector Solutions; vendor_2: Molex Connector Corporation; vendor_3: Ting Chou Metal Wire (??); vendor_part_number_2: 22-28-4060; vendor_part_number_3: 25401S1G006A101; Datasheet: \\shasdv005.infineon.com\CMU\CMU_ORCAD_CIS_LIB\CYPRESS_CIS_DATABASE\datasheet\PBC06SAAN.pdf
J37 = HDR1X10-J: CON, HDR, T/H, M, STR, 1x10P, 2.54mm, 3.05mmTL, 5.84mmPH, BREAKAWAY; BRCM PN: 535111-00; CYPN: 720-90460-01; DNI: DNI; Enviromental: RoHS; PART TYPE: HEADER_MALE; Status: APPROVED; vendor_1: Sullins Connector Solutions; Datasheet: \\shasdv005.infineon.com\CMU\CMU_ORCAD_CIS_LIB\CYPRESS_CIS_DATABASE\datasheet\PBC10SAAN.pdf
J38 = HDR2X5R-J: CONN, HEADER, MALE, 2x5P, BREAKAWAY, 2.54mm, 3.05mmTL, 5.84mmPH, STR, Au, T/H; Assembly Instructions: <Assembly Instructions>; BRCM PN: 531933-00; CYPN: 720-90494-01; DNI: DNI; Enviromental: RoHS; PART TYPE: HEADER_MALE; Status: APPROVED; vendor_1: Sullins Connector Solutions; vendor_2: Ting Chou Metal Wire (??); vendor_part_number_2: 25401S1G005A201; Datasheet: \\shasdv005.infineon.com\CMU\CMU_ORCAD_CIS_LIB\CYPRESS_CIS_DATABASE\datasheet\PBC05DAAN.pdf
R25 R38 = RES: RES, THK, 0402, 10K OHM, 5%, 63mW; Assembly Instructions: <Assembly Instructions>; BRCM PN: 500210-00; CYPN: 500-90845-01; Enviromental: RoHS; FPLIST: RESC1005_IS0402Q,RESC1005_IS0402N,RESC1005_IS0402Q_050RP; PART TYPE: THICK FILM; Size: 0402; Status: APPROVED; Tolerance: 5%; vendor_1: Walsin; vendor_2: CYNTEC; vendor_3: RALEC; vendor_4: TA-I/TYEE; vendor_5: VIKING TECH; vendor_6: Yageo America; vendor_part_number_1: WR04X103 JTL; vendor_part_number_2: PFR05S-103-JNH; vendor_part_number_3: RTT02103JTH; vendor_part_number_4: RM04JTN103; vendor_part_number_5: CR-02JL6---10KAC; vendor_part_number_6: RC0402JR-0710KL; Datasheet: \\shasdv005.infineon.com\CMU\CMU_ORCAD_CIS_LIB\CYPRESS_CIS_DATABASE\datasheet\CR..AC REV.A.pdf
R31 R33 = RES: RES, THK, 0402, 2.2K OHM, 5%, 63mW; Assembly Instructions: <Assembly Instructions>; BRCM PN: 559975-00; CYPN: 500-90839-01; Enviromental: RoHS; FPLIST: RESC1005_IS0402Q,RESC1005_IS0402N; PART TYPE: THICK FILM; Size: 0402; Status: APPROVED; Tolerance: 5%; vendor_1: CYNTEC; vendor_2: KOA Speer Electronics; vendor_3: Panasonic-ECG; vendor_4: RALEC; vendor_5: VIKING TECH; vendor_6: Walsin; vendor_part_number_1: PFR05S-222-JNH; vendor_part_number_2: RK73B1ETTP222J; vendor_part_number_3: ERJ-2GEJ222X; vendor_part_number_4: RTT02222JTH; vendor_part_number_5: CR-02JL6---2K2AC; vendor_part_number_6: WR04X222 JTL
SW2-SW4 = SW-SPST-12-34: SWH, PSH, SMT, STR, SPST-NO, 12V, 50mA, 9x6x4.3mm; CYPN: 770-90124-01; Enviromental: RoHS; PART TYPE: PUSH-BUTTON; Status: APPROVED; vendor_1: C&K Components; Datasheet: \\shasdv005.infineon.com\CMU\CMU_ORCAD_CIS_LIB\CYPRESS_CIS_DATABASE\datasheet\C&K  PTS645 Series.pdf
U10 = 74AVC4TD245BQ: IC, XLATOR, VOLTAGE LEVEL, 4-CH, BIDIR, 4 BIT, DHVQFN-16, W/EP, 2.3X3.5X0.85MM; CYPN: 450-90582-01; Enviromental: RoHS; PART TYPE: TRANSLATOR; Status: APPROVED; vendor_1: Nexperia; vendor_part_number_1: 74AVC4TD245BQ,115; Datasheet: \\shasdv005.infineon.com\CMU\CMU_ORCAD_CIS_LIB\CYPRESS_CIS_DATABASE\datasheet\74AVC4TD245BQ.pdf
U11 = SiT1532: OSC, SMT, 32.768KHz, 100PPM, 1.5/3.63V, 1.54x0.84x0.6mm, CRITICAL/SOLE SOURCE; CYPN: 540-90011-01; Critical: CRITICAL; Enviromental: RoHS; PART TYPE: OSCILLATOR; Status: APPROVED; vendor_1: SiTime; vendor_part_number_1: SiT1532AI-J4-D14-32.768E; Datasheet: \\shasdv005.infineon.com\CMU\CMU_ORCAD_CIS_LIB\CYPRESS_CIS_DATABASE\datasheet\SIT1532AI-J4-D14.pdf
ZJ21_1_2 ZJ30_1_2 ZJ30_3_4 ZJ30_5_6 ZJ30_7_8 = JUMPER: CON, JUMPER, SHORTING, .100", GOLD; Assembly Instructions: <Assembly Instructions>; CYPN: 720-90532-01; FPLIST: NA,HARDWARE; vendor_1: Sullins Connector Solutions; Datasheet: \\shasdv005.infineon.com\CMU\CMU_ORCAD_CIS_LIB\CYPRESS_CIS_DATABASE\datasheet\285_PAGE124-125_.100_JUMPER.pdf

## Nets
1.8V: J10.88 J10.90 J36.1 R26.2 R69.2 SW9.1(A1) ; also on sheet 1
3.3V: C19.1 D13.A(ANODE) D14.A(ANODE) J10.84 J10.86 J11.P15 J11.P17 R11.1 R22.1 R24.1 R406.1 SW9.3(B2) U3.3(VDD) U8.5(VCC) U9.5(VIN) ; also on sheet 1 7 11
GND: C17.2 C18.2 C19.2 C20.2 C21.1 C22.2 C23.2 C51.2 C52.1 C53.2 J5.7 J5.8 J5.13 J5.14 J5.19 J5.20 J5.25 J5.26 J5.31 J5.32 J5.37 J5.38 J5.44 J5.50 J5.55 J5.56 J5.61 J5.62 J5.67 J5.68 J5.73 J5.74 J5.79 J5.80 J5.85 J5.86 J5.91 J5.92 J5.97 J5.98 J8.2 J8.5 J8.8 J8.11 J8.17 J8.SH1(SHIELD1) J8.SH2(SHIELD2) J8.SH3(SHIELD3) J8.SH4(SHIELD4) J9.1 J10.1 J10.2 J10.7 J10.8 J10.13 J10.14 J10.22 J10.23 J10.32 J10.33 J10.42 J10.43 J10.52 J10.53 J10.59 J10.60 J10.65 J10.66 J10.71 J10.74 J10.98 J11.SH1(SHIELD1) J11.SH2(SHIELD2) J11.SH3(SHIELD3) J11.SH4(SHIELD4) J17.6(VSS) J17.11(GND1) J17.12(GND2) J17.13(GND3) J17.14(GND4) J17.15(GND5) J17.16(GND6) J23.1(GND) J23.7(GND) J23.18(GND) J23.33(GND) J23.39(GND) J23.45(GND) J23.51(GND) J23.57(GND) J23.63(GND) J23.69(GND) J23.75(GND) J37.10 J38.2(P2) J38.4(P4) J38.6(P6) J38.8(P8) J38.10(P10) J49.2 R44.1 R45.1 R52.1 SW8.9(B8) SW8.10(B7) SW8.11(B6) SW8.12(B5) SW8.13(B4) SW8.14(B3) SW8.15(B2) SW8.16(B1) U3.4(GND) U4.3(GND) U6.3(GND1) U6.8(GND2) U7.3(GND1) U7.8(GND2) U8.3(GND) U9.2(GND) U10.8(GND) U10.9(OE) U10.10(DIR3) U10.EP(EPAD) U11.1(GND1) U11.4(GND4) U15.2(GND) U15.5(DIR) ; also on sheet 1 2 3 7 11
VBAT: J21.2 J23.2(3.3_V) J23.4(3.3_V) J23.72(3.3_V) J23.74(3.3_V)
VDD_5V: J10.77 J10.79 J10.81 J10.83 J10.85 J10.87 ; also on sheet 1 11
VDDIO: J23.64(RESERVED) J36.2
BT_DBG_CTS: J23.67(RESERVED/PETN1) J37.5
BT_DBG_RTS: J23.65(RESERVED/PETP1) J37.4
BT_DBG_RX: J23.73(RESERVED/REFCLKN1) J37.7 R53.1
BT_DBG_TX: J23.71(RESERVED/REFCLKP1) J37.6 R88.1
BT_HOST_WAKE: J35.6 R86.2 U10.5(A3)
BT_HOST_WAKE_3P3: J23.20(UART_WAKE#_(O)(0/3.3V)) R34.2
BT_nDis: J10.91 SW8.4(A4)
BT_REG_ON_3P3: J23.54(W_DISABLE2#_(I)(0/3.3V)) R25.2 R33.2 SW2.3(C) SW2.4(D) SW8.8(A8)
CTS: R98.2 ; also on sheet 1
EEPROM_nWP: J10.20 SW8.6(A6)
ETH_LEDG: J10.15 R14.1
ETH_LEDY: J10.17 R13.1
EXT_LPO: U10.6(A4) U11.2(OUT)
EXT_LPO_3P3: R48.1 U10.11(B4)
GLOBAL_EN: J10.99 SW8.1(A1)
GPIO2: J10.58 U10.3(A1)
GPIO3: J10.56 U10.4(A2)
GPIO4: J10.54 J23.42(VENDOR_DEFINED_3) TP38.1(TP)
GPIO5: J10.34 R37.2
GPIO6: J10.30 U15.3(A)
GPIO6_3P3: R51.2 U15.4(B)
GPIO7: J10.37 R39.2
GPIO8: J10.39 R57.1 R95.1
GPIO9: J10.40 R55.1 R96.1
GPIO10: J10.44 R53.2 R97.1
GPIO11: J10.38 R54.1 R98.1
GPIO12: J10.31 R86.1 R87.1
GPIO13: J10.28 R88.2 R89.2
GPIO14: J10.55 J30.3(P3)
GPIO15: J10.51 J30.1(P1)
GPIO16: J10.29 J30.5(P5)
GPIO17: J10.50 J30.7(P7)
GPIO18: J10.49 J25.1(P1)
GPIO19: J10.26 J25.3(P3)
GPIO20: J10.27 J25.5(P5)
GPIO21: J10.25 J25.7(P7)
GPIO22: J10.46 R28.2
GPIO23: J10.47 R29.2
GPIO24: J10.45 R30.2
GPIO25: J10.41 R32.2
GPIO26: J10.24 R35.2
GPIO27: J10.48 R36.2
GPIO_VREF: J10.78 SW9.2(A2)
HD1_M2_N: J23.5(USB_D-) ; also on sheet 7
HD1_M2_P: J23.3(USB_D+) ; also on sheet 7
HDMI0_CEC: J5.51 J8.13
HDMI0_CK_N: J5.90 J8.12
HDMI0_CK_P: J5.88 J8.10
HDMI0_D0_N: J5.84 J8.9
HDMI0_D0_P: J5.82 J8.7
HDMI0_D1_N: J5.78 J8.6
HDMI0_D1_P: J5.76 J8.4
HDMI0_D2_N: J5.72 J8.3
HDMI0_D2_P: J5.70 J8.1
HDMI0_HOTPLUG: J5.53 J8.19
HDMI0_SCL: J5.100 J8.15
HDMI0_SDA: J5.99 J8.16
HDMI_5V: C18.1 J8.18 U4.2(VOUT)
ID_SC: J10.35 TP2.1(TP)
ID_SD: J10.36 TP1.1(TP)
LED1: J23.6(LED_1#_(O)(OD)) J37.8
LED2: J23.16(LED_2#_(O)(OD)) J37.9
M2_GPIO1: J23.59(RESERVED/PERP1) J37.2
M2_GPIO2: J23.61(RESERVED/PERN1) J37.3
M2_VBAT: C23.1 J21.1 J37.1 R25.1 R27.2 R38.1 R70.2 U11.3(VDD) ; also on sheet 11
nEXTRST: J10.100 ; also on sheet 7
nLED_ACTIVITY: J10.21 R12.2
nPWR_LED: J10.95 U8.2(A)
nRPIBOOT: J10.93 SW8.5(A5)
PCIE_CLK_N: J5.12 R47.2
PCIE_CLK_nREQ_3P3: J5.2 R50.2
PCIE_CLK_P: J5.10 R46.2
PCIE_nRST_3P3: J5.9 R49.1
PCIE_PME_L: J23.55(PEWAKE0#_(I/O)(0/3.3V)) R51.1
PCIE_RX_N: J5.18 R43.2
PCIE_RX_P: J5.16 R42.2
PCIE_TX_N: J5.24 R41.2
PCIE_TX_P: J5.22 R40.2
PERI_5V: C17.1 J9.2 U4.1(VIN) ; also on sheet 7 11
PWM0_0: R87.2 ; also on sheet 3
PWM0_1: R89.1 ; also on sheet 3
RTS: R97.2 ; also on sheet 1
RUN_PG: J10.92 J49.1 SW8.2(A2)
RXD: R95.2 ; also on sheet 1
SCL0: J10.80 U3.2(SMCLK)
SD_CLK: J10.57 R18.1
SD_CMD: J10.62 R17.1
SD_DAT0: J10.63 R19.1
SD_DAT1: J10.67 R20.1
SD_DAT2: J10.69 R15.1
SD_DAT3: J10.61 R16.1
SD_DET: J10.76 R23.1
SD_PWR: C20.1 J17.4(VDD) U9.1(VOUT)
SD_PWR_ON: J10.75 R24.2 U9.4(EN)
SDA0: J10.82 U3.1(SMDATA)
TR0_TAP: J11.P11 TP12.1(TP)
TR1_TAP: J11.P12 TP10.1(TP)
TR2_TAP: J11.P13 TP11.1(TP)
TR3_TAP: J11.P14 TP13.1(TP)
TRD0_N: J10.10 J11.P2 U7.4(D2_P)
TRD0_P: J10.12 J11.P1 U7.5(D2_N)
TRD1_N: J10.6 J11.P6 U7.1(D1_P)
TRD1_P: J10.4 J11.P3 U7.2(D1_N)
TRD2_N: J10.9 J11.P8 U6.5(D2_N)
TRD2_P: J10.11 J11.P7 U6.4(D2_P)
TRD3_N: J10.5 J11.P10 U6.2(D1_N)
TRD3_P: J10.3 J11.P9 U6.1(D1_P)
TXD: R96.2 ; also on sheet 1
UART_CTS: J23.36(UART_CTS_(I)(0/1.8V)) J30.8(P8) SW4.3(C) SW4.4(D)
USB2_N: J5.3 ; also on sheet 7
USB2_P: J5.5 ; also on sheet 7
USBOTG: J5.1 ; also on sheet 7
WL_HOST_WAKE: J23.21(SDIO_WAKE#_(O)(0/1.8V)) J35.5 R37.1
WL_JTAG_TCK: J23.46(COEX_TXD_(O)(0/1.8V)) J38.9(P9)
WL_JTAG_TDI: J23.40(VENDOR_DEFINED_2) J38.3(P3)
WL_JTAG_TDO: J23.38(VENDOR_DEFINED_1) J38.5(P5)
WL_JTAG_TMS: J23.48(COEX_RXD_(I)(0/1.8V)) J38.7(P7)
WL_JTAG_TRST: J23.44(COEX3_(I/O)(0/1.8V)) J38.1(P1)
WL_nDis: J10.89 SW8.3(A3)
WL_REG_ON_3P3: J23.56(W_DISABLE1#_(I)(0/3.3V)) R31.2 R38.2 SW3.3(C) SW3.4(D) SW8.7(A7)
WL_UART_CTS: J23.66(UIM_SWP/PERST1#) J35.3 R54.2
WL_UART_RTS: J23.62(ALERT#_(O)(0/1.8_V)) J35.4
WL_UART_RXD: J23.70(UIM_POWER_SRC/GPIO1/PEWAKE1#) J35.2 R57.2
WL_UART_TXD: J23.68(UIM_POWER_SNK/CLKREQ1#) J35.1 R55.2
N17463017: C53.1 J11.P4 J11.P5
N17463374: J11.P16 R13.2
N17463377: J11.P18 R14.2
N17465158: D14.C(CATHODE) R21.1
N17465213: R21.2 U8.4(Y)
N17469381: J17.9(SWA) R23.2
N17469410: J17.10(SWB) R22.2
N17494894: J23.53(CLKREQ0#_(I/O)(0/3.3V)) R50.1
N17494904: J23.47(REFCLKP0) R46.1
N17494909: J23.49(REFCLKN0) R47.1
N17494920: J23.35(PERP0) R40.1
N17494923: J23.37(PERN0) R41.1
N17494926: J23.41(PETP0) R42.1
N17494929: J23.43(PETN0) R43.1
N17499052: J23.9(SDIO_CLK/SYSCLK_(I)(0/1.8V)) R28.1
N17499057: J23.11(SDIO_CMD_(I/O)(0/1.8V)) R29.1
N17499218: J23.13(SDIO_DATA0_(I/O)(0/1.8V)) R30.1
N17499237: J23.15(SDIO_DATA1_(I/O)(0/1.8V)) R32.1
N17499256: J23.17(SDIO_DATA2_(I/O)(0/1.8V)) R35.1
N17499275: J23.19(SDIO_DATA3_(I/O)(0/1.8V)) R36.1
N17499655: J23.52(PERST0#_(I)(0/3.3V)) R49.2
N17540958: C21.2 R26.1 U10.1(VCCA) U10.2(DIR1) U10.7(DIR4) U10.15(DIR2)
N17540970: C22.1 R27.1 U10.16(VCCB)
N17541044: R31.1 U10.14(B1)
N17541046: R33.1 U10.13(B2)
N17541095: R34.1 U10.12(B3)
N17548832: J23.8(PCM_CLK/I2S_SCK_(I/O)(0/1.8V)) J25.2(P2)
N17548852: J23.10(PCM_SYNC/I2S_WS_(I/O)(0/1.8V)) J25.4(P4)
N17549259: J23.50(SUSCLK(32KHZ)_(I)(0/3.3V)) R48.2
N17549874: R44.2 SW2.1(A) SW2.2(B)
N17549924: R45.2 SW3.1(A) SW3.2(B)
N17560700: J23.23(SDIO_RESET#/TX_BLANKING_(I)(0/1.8V)) R39.1
N17563208: R52.2 SW4.1(A) SW4.2(B)
N17565806: J23.12(PCM_OUT/I2S_SD_OUT_(O)(0/1.8V)) J25.6(P6)
N17565868: J23.14(PCM_IN/I2S_SD_IN_(I)(0/1.8V)) J25.8(P8)
N17568318: J17.1(DAT2) R15.2
N17568347: J17.2(DAT3/CD) R16.2
N17568375: J17.3(CMD) R17.2
N17568415: J17.5(CLK) R18.2
N17569067: J17.7(DAT0) R19.2
N17569095: J17.8(DAT1) R20.2
N17579667: J9.4 U3.5(PWM)
N17579869: J9.3 R11.2 U3.6(TACH)
N17596444: J23.34(UART_RTS_(O)(0/1.8V)) J30.6(P6)
N17596453: J23.32(UART_RXD_(I)(0/1.8V)) J30.4(P4)
N17596462: J23.22(UART_TXD_(O)(0/1.8V)) J30.2(P2)
N17603435: C52.2 R69.1 U15.1(VCCA)
N17603462: C51.1 R70.1 U15.6(VCCB)
N17801368: J5.6 R406.2
N17887767: D13.C(CATHODE) R12.1

Not connected (* = marked no-connect by the designer): J5 4* 11* 15* 17* 21* 23* 27* 28* 29* 30* 33* 34* 35* 36* 39* 40* 41* 42* 43* 45* 46* 47* 48* 49* 52* 54* 57* 58* 59* 60* 63* 64* 65* 66* 69* 71* 75* 77* 81* 83* 87* 89* 93* 94* 95* 96*; J8 14; J10 16* 18* 19* 64* 68* 70* 72* 73* 94* 96* 97*; J23 58(I2C_DATA_(I/O)(0/1.8_V))* 60(I2C_CLK_(I)(0/1.8_V))*; U3 7(CLK)* 8(~{ALERT})*; U6 6(NC1)* 7(NC2)* 9(NC3)* 10(NC4)*; U7 6(NC1)* 7(NC2)* 9(NC3)* 10(NC4)*; U9 3(~{FLG})*

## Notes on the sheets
sheet 8
- RPi CM4 Connector 1
- GPIO Level Translator
- Port A
  To Raspberry Pi CM4
- Port B
  To M.2 Socket
- HDMI Connector
- Fan Controller
sheet 9
- RPi CM4 Connector 2
- 1G Ethernet Interface
- Activity LED
- CM4 GPIO Voltage Select
- SD Card Interface
- (Default set to 1.8V)
- Power LED
- Place on Tri-pad
sheet 10
- M.2 Interface
- M.2 Level Translator
- Port A
  To Raspberry Pi CM4
- Port B
  To M.2 Socket
- BT Reset Button
- WL Reset Button
- BT_DEV_WAKE
- Autobaud Button
- On-Board LPO
  (SiTime)
- UART, JTAG & GPIO Headers
